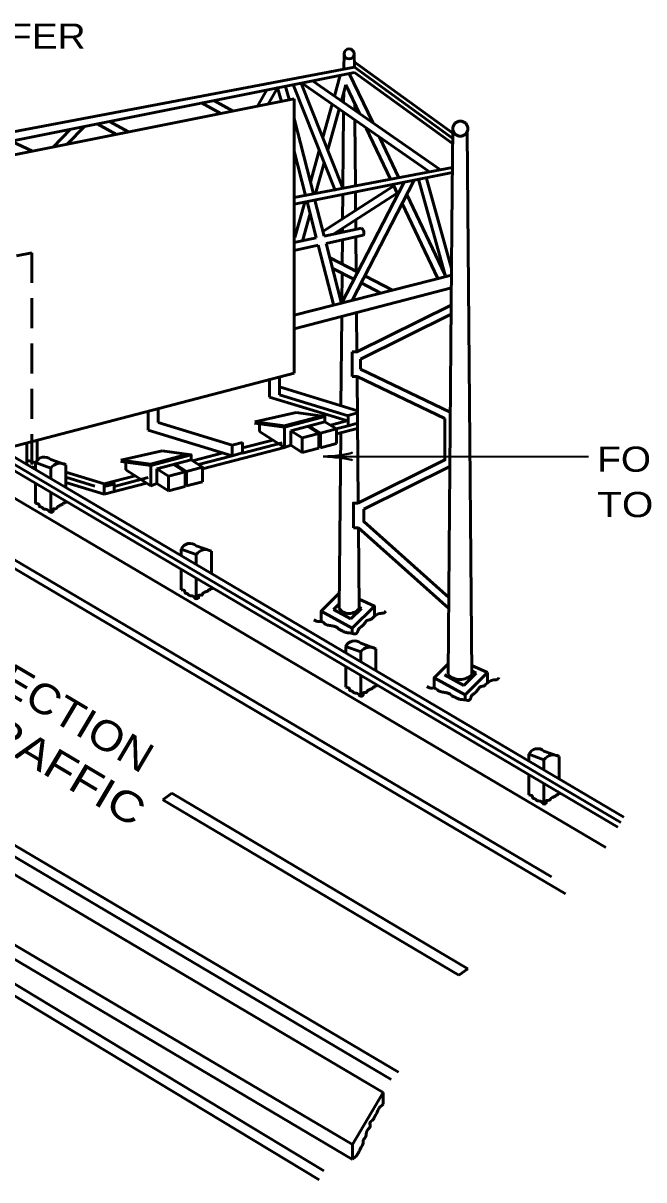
# Model space of a CAD drawing. Extents: x -111 to 744, y -77 to 467.
# Drawn here: x 572.7 to 646.6, y 206.5 to 344.2 of the extents above; entities that cross this region are included whole.
import ezdxf
from ezdxf.enums import TextEntityAlignment as Align

# ---------------------------------------------------------------- set-up
doc = ezdxf.new("R2010")
doc.units = 0
doc.header["$LTSCALE"] = 1.2
doc.linetypes.add('MEDIUM_DASHED', pattern=[4.5, 3, -1.5])
doc.layers.add('1', color=7, linetype='Continuous', lineweight=53)

msp = doc.modelspace()

# ---------------------------------------------------------------- linework, layer by layer
at = {"layer": '1'}
for p, q in [((610.927, 340.574), (610.912, 338.742)), ((612.142, 340.585), (612.156, 338.978)), ((612.15, 339.648), (623.865, 331.154)), ((612.156, 338.978), (623.86, 330.493)), ((561.783, 328.297), (612.161, 338.374)), ((610.46, 338.034), (609.772, 335.562)), ((611.554, 338.253), (614.335, 332.39)), ((612.161, 338.374), (623.855, 329.897)), ((600.633, 334.347), (601.743, 336.29)), ((603.91, 336.817), (604.399, 335.193)), ((604.907, 336.799), (609.895, 324.22)), ((605.799, 337.153), (610.788, 324.574)), ((605.857, 337.113), (621.093, 326.525)), ((607.163, 337.375), (622.415, 326.776)), ((611.138, 336.891), (610.606, 334.982)), ((611.138, 336.891), (612.75, 333.492)), ((569.111, 328.042), (604.991, 335.219)), ((593.955, 334.733), (596.254, 333.471)), ((595.418, 335.025), (597.716, 333.764)), ((604.991, 335.219), (604.991, 302.569)), ((610.887, 335.991), (610.877, 334.794)), ((609.499, 334.582), (608.394, 330.611)), ((610.334, 334.002), (608.979, 329.134)), ((610.867, 333.632), (610.788, 324.574)), ((612.193, 334.666), (612.2, 333.874)), ((577.957, 329.811), (580.024, 331.946)), ((581.523, 332.245), (583.822, 330.984)), ((582.985, 332.538), (585.284, 331.277)), ((604.991, 332.871), (607.278, 323.909)), ((612.21, 332.698), (612.279, 324.856)), ((576.299, 329.48), (578.366, 331.614)), ((613.577, 331.748), (616.471, 325.65)), ((615.163, 330.647), (617.446, 325.835)), ((623.806, 324.286), (623.87, 331.673)), ((625.58, 331.281), (626.143, 266.728)), ((571.288, 330.198), (573.849, 328.989)), ((604.991, 328.993), (606.334, 323.73)), ((607.968, 329.081), (606.92, 325.314)), ((604.991, 323.476), (623.83, 327.044)), ((604.991, 322.675), (623.824, 326.443)), ((608.553, 327.604), (607.539, 323.958)), ((610.612, 310.844), (618.071, 325.292)), ((611.884, 311.215), (619.276, 325.533)), ((622.949, 314.234), (619.831, 325.49)), ((623.725, 315.03), (620.756, 325.747)), ((608.419, 319.439), (616.85, 324.85)), ((609.799, 319.184), (617.265, 323.976)), ((610.781, 323.834), (610.756, 320.939)), ((612.285, 324.135), (612.304, 321.933)), ((616.764, 325.031), (617.326, 323.848)), ((618.397, 323.83), (622.949, 314.234)), ((623.806, 324.286), (623.688, 310.786)), ((606.256, 322.929), (605.078, 318.696)), ((606.525, 322.982), (607.624, 318.674)), ((607.466, 323.171), (608.563, 318.873)), ((617.843, 322.757), (622.082, 313.823)), ((606.88, 321.591), (606.003, 318.438)), ((608.563, 318.873), (613.005, 319.813)), ((610.746, 319.792), (610.742, 319.334)), ((612.314, 320.798), (612.324, 319.669)), ((604.991, 318.116), (607.624, 318.674)), ((608.785, 318.004), (613.211, 318.98)), ((610.734, 318.434), (610.709, 315.552)), ((612.332, 318.786), (612.367, 314.692)), ((604.991, 317.167), (607.848, 317.797)), ((607.848, 317.797), (609.693, 310.567)), ((608.785, 318.004), (610.612, 310.844)), ((609.213, 316.327), (612.55, 314.598)), ((604.991, 309.452), (623.718, 314.243)), ((609.531, 315.081), (612.11, 313.745)), ((610.699, 314.476), (610.668, 310.904)), ((613.402, 314.156), (616.7, 312.447)), ((604.991, 307.832), (623.705, 312.723)), ((612.962, 313.303), (615.303, 312.09)), ((623.688, 310.786), (623.303, 266.728)), ((610.654, 309.312), (610.562, 298.68)), ((612.877, 304.235), (623.677, 309.588)), ((611.876, 305.096), (611.876, 302.164)), ((612.451, 305.096), (611.876, 305.096)), ((544.381, 303.796), (642.104, 246.088)), ((612.877, 303.037), (612.877, 304.235)), ((612.877, 303.037), (623.576, 297.927)), ((569.111, 293.191), (604.991, 302.569)), ((602.05, 301.8), (602.05, 299.714)), ((603.25, 302.114), (603.25, 299.975)), ((612.476, 302.164), (611.876, 302.164)), ((612.476, 302.164), (622.936, 297.169)), ((612.476, 302.164), (612.608, 287.122)), ((603.25, 300.916), (612.512, 298.084)), ((602.05, 299.714), (611.23, 296.907)), ((603.25, 299.975), (611.405, 297.481)), ((587.612, 298.027), (587.612, 295.784)), ((588.812, 298.34), (588.812, 296.672)), ((600.298, 296.747), (605.207, 297.865)), ((612.514, 297.827), (611.405, 297.539)), ((562.057, 296.609), (643.527, 248.499)), ((562.965, 296.847), (643.866, 249.073)), ((563.952, 297.105), (644.234, 249.696)), ((588.812, 296.672), (597.619, 293.979)), ((600.279, 296.599), (603.852, 296.141)), ((600.298, 296.747), (603.871, 296.29)), ((600.874, 295.622), (600.874, 296.522)), ((603.814, 296.286), (608.262, 297.456)), ((603.852, 293.697), (603.852, 296.141)), ((604.585, 295.713), (608.652, 296.784)), ((606.563, 296.234), (607.933, 295.366)), ((606.745, 296.282), (608.116, 295.414)), ((608.652, 296.784), (608.652, 297.404)), ((611.255, 296.88), (609.3, 296.373)), ((611.405, 296.3), (609.995, 295.934)), ((611.405, 297.481), (611.405, 296.281)), ((612.525, 296.59), (611.405, 296.3)), ((587.612, 295.784), (597.619, 292.724)), ((600.874, 295.622), (603.852, 293.697)), ((604.585, 293.988), (604.585, 295.713)), ((605.956, 294.846), (607.933, 295.366)), ((607.933, 295.366), (607.933, 293.64)), ((608.116, 295.414), (610.023, 295.916)), ((608.116, 295.414), (608.116, 293.688)), ((612.531, 295.971), (610.023, 295.321)), ((610.534, 295.454), (610.351, 274.545)), ((573.174, 294.253), (573.174, 291.659)), ((574.374, 294.567), (574.374, 292.163)), ((603.826, 293.714), (594.093, 291.19)), ((597.619, 293.979), (598.819, 294.303)), ((597.619, 292.736), (597.619, 293.979)), ((602.457, 294.599), (598.819, 293.655)), ((598.819, 293.036), (598.819, 294.303)), ((603.571, 294.268), (598.819, 293.036)), ((605.956, 293.12), (607.933, 293.64)), ((608.116, 293.688), (610.023, 294.19)), ((548.408, 293.041), (637.3, 240.548)), ((549.63, 293.361), (635.614, 242.585)), ((573.174, 292.208), (574.374, 291.841)), ((576.013, 292.288), (577.812, 291.635)), ((584.349, 292.041), (587.923, 291.583)), ((584.368, 292.189), (589.278, 293.307)), ((584.368, 292.189), (587.942, 291.732)), ((587.885, 291.728), (592.332, 292.898)), ((588.656, 291.155), (592.723, 292.226)), ((592.723, 292.226), (592.723, 292.846)), ((596.522, 293.06), (592.892, 292.118)), ((597.619, 292.724), (593.587, 291.679)), ((597.619, 292.736), (598.958, 293.098)), ((574.212, 291.907), (576.013, 291.254)), ((574.212, 291.907), (574.212, 291.094)), ((576.013, 291.254), (576.013, 290.031)), ((577.812, 291.635), (577.812, 288.968)), ((577.812, 290.79), (582.382, 289.393)), ((584.945, 291.064), (584.945, 291.964)), ((584.945, 291.064), (587.923, 289.139)), ((587.923, 289.139), (587.923, 291.583)), ((588.656, 289.43), (588.656, 291.155)), ((590.026, 290.288), (592.003, 290.808)), ((590.633, 291.676), (592.003, 290.808)), ((590.816, 291.724), (592.186, 290.856)), ((592.004, 290.808), (592.004, 289.082)), ((592.186, 290.856), (594.093, 291.358)), ((592.186, 290.856), (592.186, 289.13)), ((613.273, 286.381), (623.519, 291.459)), ((574.212, 289.48), (574.212, 287.058)), ((577.812, 289.535), (582.355, 288.146)), ((587.425, 289.461), (582.355, 288.146)), ((582.355, 288.146), (582.355, 289.346)), ((586.056, 290.346), (582.382, 289.393)), ((583.555, 289.346), (583.521, 289.647)), ((587.614, 290.13), (583.555, 289.077)), ((592.186, 289.13), (594.093, 289.632)), ((576.013, 288.417), (576.013, 285.979)), ((590.026, 288.562), (592.004, 289.082)), ((577.812, 287.354), (577.812, 287.058)), ((612.634, 284.165), (612.034, 284.165)), ((623.372, 274.566), (612.634, 284.165)), ((612.634, 284.165), (612.717, 274.565)), ((508.086, 282.502), (616.534, 218.46)), ((509.722, 282.929), (617.424, 219.328)), ((505.632, 281.86), (615.584, 216.93)), ((591.538, 281.622), (593.338, 280.97)), ((591.538, 281.622), (591.538, 280.809)), ((593.338, 282.003), (595.138, 281.35)), ((593.338, 280.97), (593.338, 279.746)), ((595.138, 281.35), (595.138, 278.684)), ((494.032, 278.828), (611.923, 208.935)), ((495.817, 279.295), (611.923, 210.731)), ((591.538, 279.195), (591.538, 276.773)), ((490.056, 277.789), (607.956, 206.509)), ((491.676, 278.212), (608.519, 207.571)), ((593.338, 278.132), (593.338, 275.694)), ((595.138, 277.069), (595.138, 276.773)), ((608.185, 274.204), (611.894, 272.18)), ((610.356, 275.102), (609.672, 274.418)), ((609.672, 274.418), (611.734, 273.293)), ((612.99, 274.549), (611.734, 273.293)), ((612.716, 274.672), (612.99, 274.549)), ((614.548, 274.834), (614.548, 273.634)), ((611.894, 272.18), (611.894, 271.599)), ((611.127, 270.02), (612.927, 269.367)), ((611.127, 270.02), (611.127, 269.207)), ((612.927, 270.401), (614.727, 269.748)), ((612.927, 269.367), (612.927, 268.144)), ((614.727, 269.748), (614.727, 267.081)), ((611.127, 267.593), (611.127, 265.171)), ((626.134, 267.748), (628.005, 266.904)), ((612.927, 266.53), (612.927, 264.091)), ((621.643, 266.274), (625.352, 264.25)), ((622.866, 266.632), (625.191, 265.363)), ((626.66, 266.831), (625.191, 265.363)), ((628.005, 266.904), (625.352, 264.25)), ((626.14, 267.115), (626.66, 266.831)), ((628.005, 266.904), (628.005, 265.704)), ((614.727, 265.467), (614.727, 265.171)), ((625.352, 264.25), (625.352, 263.669)), ((634.73, 257.565), (636.53, 256.912)), ((632.93, 257.184), (634.73, 256.531)), ((632.93, 257.184), (632.93, 256.371)), ((634.73, 256.531), (634.73, 255.308)), ((636.53, 256.912), (636.53, 254.245)), ((632.93, 254.757), (632.93, 252.335)), ((634.73, 253.694), (634.73, 251.256)), ((590.411, 252.548), (589.369, 251.771)), ((590.411, 252.549), (625.648, 231.644)), ((636.53, 252.631), (636.53, 252.335)), ((589.37, 251.771), (624.606, 230.866)), ((625.648, 231.644), (624.606, 230.866)), ((615.584, 216.93), (611.923, 210.731)), ((615.584, 216.93), (615.584, 215.523)), ((611.923, 210.731), (611.923, 208.987))]:
    msp.add_line(p, q, dxfattribs=at)
at = {"layer": '1', "linetype": 'MEDIUM_DASHED'}
for p, q in [((573.774, 316.904), (573.774, 291.397)), ((573.774, 291.397), (574.212, 291.263)), ((577.812, 290.162), (582.206, 288.819))]:
    msp.add_line(p, q, dxfattribs=at)
at = {"layer": '1', "lineweight": 35}
msp.add_line((608.472, 292.644), (640.025, 292.644), dxfattribs=at)
at = {"layer": '1'}
for points in [[(431.101, 304.698), (431.997, 304.857), (612.156, 338.978)], [(601.881, 334.597), (602.991, 336.54), (603.479, 334.917)], [(612.41, 309.771), (612.451, 305.096), (623.687, 310.664)], [(603.852, 296.141), (608.652, 297.404), (605.207, 297.865)], [(608.652, 296.784), (610.023, 295.916), (610.023, 294.19)], [(612.555, 287.096), (622.936, 292.241), (622.936, 297.169)], [(604.585, 295.713), (605.956, 294.846), (605.956, 293.12)], [(603.852, 293.697), (604.585, 293.988), (605.956, 293.12)], [(587.923, 291.583), (592.723, 292.846), (589.278, 293.307)], [(592.723, 292.226), (594.093, 291.358), (594.093, 289.632)], [(588.656, 291.155), (590.026, 290.288), (590.026, 288.562)], [(583.555, 288.457), (583.555, 289.346), (582.382, 289.05)], [(587.923, 289.139), (588.656, 289.43), (590.026, 288.562)], [(612.555, 287.096), (612.034, 287.096), (612.034, 284.165)], [(623.383, 275.844), (613.273, 284.881), (613.273, 286.381)], [(610.367, 276.386), (608.185, 274.204), (608.185, 273.004)], [(612.708, 275.664), (614.548, 274.834), (611.894, 272.18)], [(623.314, 267.945), (621.643, 266.274), (621.643, 265.074)]]:
    msp.add_lwpolyline(points, dxfattribs=at)
at = {"layer": '1', "linetype": 'MEDIUM_DASHED'}
msp.add_lwpolyline([(450.353, 293.059), (471.201, 297.019), (573.774, 316.904)], dxfattribs=at)
at = {"layer": '1'}
for centre, radius in [((611.527, 340.574), 0.6), ((624.77, 331.673), 0.9)]:
    msp.add_circle(centre, radius, dxfattribs=at)
for centre, radius, start, end in [((612.699, 319.296), 0.601, 328.33099, 59.40133), ((575.255, 291.425), 1.148, 48.69365, 155.19657), ((577.114, 290.494), 1.339, 58.52834, 145.36189), ((592.58, 281.141), 1.148, 48.69365, 155.19657), ((594.439, 280.209), 1.339, 58.52834, 145.36189), ((611.527, 275.407), 1.458, 216.25079, 324.74685), ((612.169, 269.538), 1.148, 48.69365, 155.19657), ((614.029, 268.606), 1.339, 58.52834, 145.36189), ((624.723, 267.954), 1.876, 220.82266, 319.17734), ((633.972, 256.702), 1.148, 48.69365, 155.19657), ((635.831, 255.771), 1.339, 58.52834, 145.36189)]:
    msp.add_arc(centre, radius, start, end, dxfattribs=at)
at = {"layer": '1', "lineweight": 40}
for centre, major_axis, ratio, start_param, end_param in [((609.816, 292.39), (-2.108, 0.211), 0.07063, 3.1407148, 5.41811), ((609.781, 292.976), (-2.143, -0.187), 0.122415, 0.8963533, 3.1415927)]:
    msp.add_ellipse(centre, major_axis=major_axis, ratio=ratio, start_param=start_param, end_param=end_param, dxfattribs=at)
at = {"layer": '1'}
for points in [[(574.212, 287.058), (574.648, 286.849), (574.648, 286.74), (574.811, 286.631), (574.865, 286.631), (575.082, 286.468), (575.137, 286.414), (575.626, 286.305), (576.013, 285.979), (576.279, 286.088), (576.279, 286.251), (576.279, 286.36), (576.714, 286.468), (576.768, 286.577), (576.985, 286.74), (577.094, 286.795), (577.42, 286.958), (577.529, 287.067), (577.638, 287.121), (577.812, 287.058)], [(591.538, 276.773), (591.973, 276.564), (591.973, 276.455), (592.136, 276.346), (592.191, 276.346), (592.408, 276.183), (592.462, 276.129), (592.952, 276.02), (593.338, 275.694), (593.604, 275.803), (593.604, 275.966), (593.604, 276.075), (594.039, 276.183), (594.094, 276.292), (594.311, 276.455), (594.42, 276.51), (594.746, 276.673), (594.855, 276.782), (594.964, 276.836), (595.138, 276.773)], [(607.345, 273.187), (607.96, 272.989), (608.201, 273.011), (608.355, 272.945), (608.816, 272.616), (609.321, 272.506), (609.738, 272.418), (610.112, 272.264), (610.309, 272.088), (610.617, 271.935), (611.012, 271.737), (611.166, 271.693), (611.539, 271.627), (611.913, 271.583), (612.198, 271.517), (612.418, 271.583), (612.571, 271.869), (612.747, 272.198), (612.857, 272.264), (613.098, 272.462), (613.23, 272.594), (613.428, 272.857), (613.625, 273.099), (613.955, 273.209), (614.306, 273.384), (614.504, 273.582), (614.658, 273.714), (614.899, 273.846), (615.426, 273.978), (615.756, 274.043), (615.909, 274.241)], [(620.802, 265.257), (621.417, 265.059), (621.659, 265.081), (621.812, 265.015), (622.274, 264.686), (622.779, 264.576), (623.196, 264.488), (623.569, 264.334), (623.767, 264.159), (624.074, 264.005), (624.47, 263.807), (624.623, 263.763), (624.997, 263.697), (625.37, 263.653), (625.656, 263.587), (625.875, 263.653), (626.029, 263.939), (626.205, 264.268), (626.314, 264.334), (626.556, 264.532), (626.688, 264.664), (626.885, 264.927), (627.083, 265.169), (627.413, 265.279), (627.764, 265.455), (627.962, 265.652), (628.115, 265.784), (628.357, 265.916), (628.884, 266.048), (629.213, 266.114), (629.367, 266.311)], [(611.127, 265.171), (611.562, 264.962), (611.562, 264.853), (611.725, 264.744), (611.78, 264.744), (611.997, 264.581), (612.052, 264.527), (612.541, 264.418), (612.927, 264.091), (613.193, 264.2), (613.193, 264.363), (613.193, 264.472), (613.628, 264.581), (613.683, 264.69), (613.9, 264.853), (614.009, 264.907), (614.335, 265.07), (614.444, 265.179), (614.553, 265.234), (614.727, 265.171)], [(632.93, 252.335), (633.365, 252.126), (633.365, 252.017), (633.528, 251.908), (633.582, 251.908), (633.8, 251.745), (633.854, 251.691), (634.344, 251.582), (634.73, 251.256), (634.996, 251.365), (634.996, 251.528), (634.996, 251.637), (635.431, 251.745), (635.485, 251.854), (635.703, 252.017), (635.812, 252.072), (636.138, 252.235), (636.247, 252.344), (636.355, 252.398), (636.53, 252.335)], [(611.923, 208.987), (612.325, 209.307), (612.397, 209.379), (612.576, 209.63), (612.791, 210.059), (612.969, 210.417), (613.113, 210.632), (613.22, 210.882), (613.22, 211.24), (613.399, 211.491), (613.578, 211.992), (613.792, 212.564), (614.043, 212.851), (614.007, 213.28), (614.365, 213.674), (614.544, 213.996), (614.83, 214.461), (615.009, 214.891), (615.584, 215.523)]]:
    msp.add_spline(points, degree=3, dxfattribs=at)

# ---------------------------------------------------------------- texts
for s, width, p in [('FOR CONNECTION DETAILS REFER', 1.15, (500.701, 341.194)), ('FOR FIXTURE DETAILS REFER', 1.15, (641.065, 290.821)), ('TO STANDARD SHEET TE6-3C.', 1.2, (641.065, 285.421))]:
    msp.add_text(s, height=3, dxfattribs=dict(at, width=width)).set_placement(p)
for s, width, p in [('DIRECTION', 1.1, (574.302, 262.269)), ('OF TRAFFIC', 1.2, (571.241, 257.109))]:
    msp.add_text(s, height=3.6, rotation=329.321, dxfattribs=dict(at, width=width)).set_placement(p, align=Align.CENTER)

doc.saveas('drawing.dxf')
